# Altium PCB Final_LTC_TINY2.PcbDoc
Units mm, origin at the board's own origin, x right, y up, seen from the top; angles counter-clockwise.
Board outline 34.19 x 13.74 mm, 2 copper layers (Top Layer, Bottom Layer), stack 1.671 mm thick; 36 components, 55 nets, 138 pads, 94 vias.
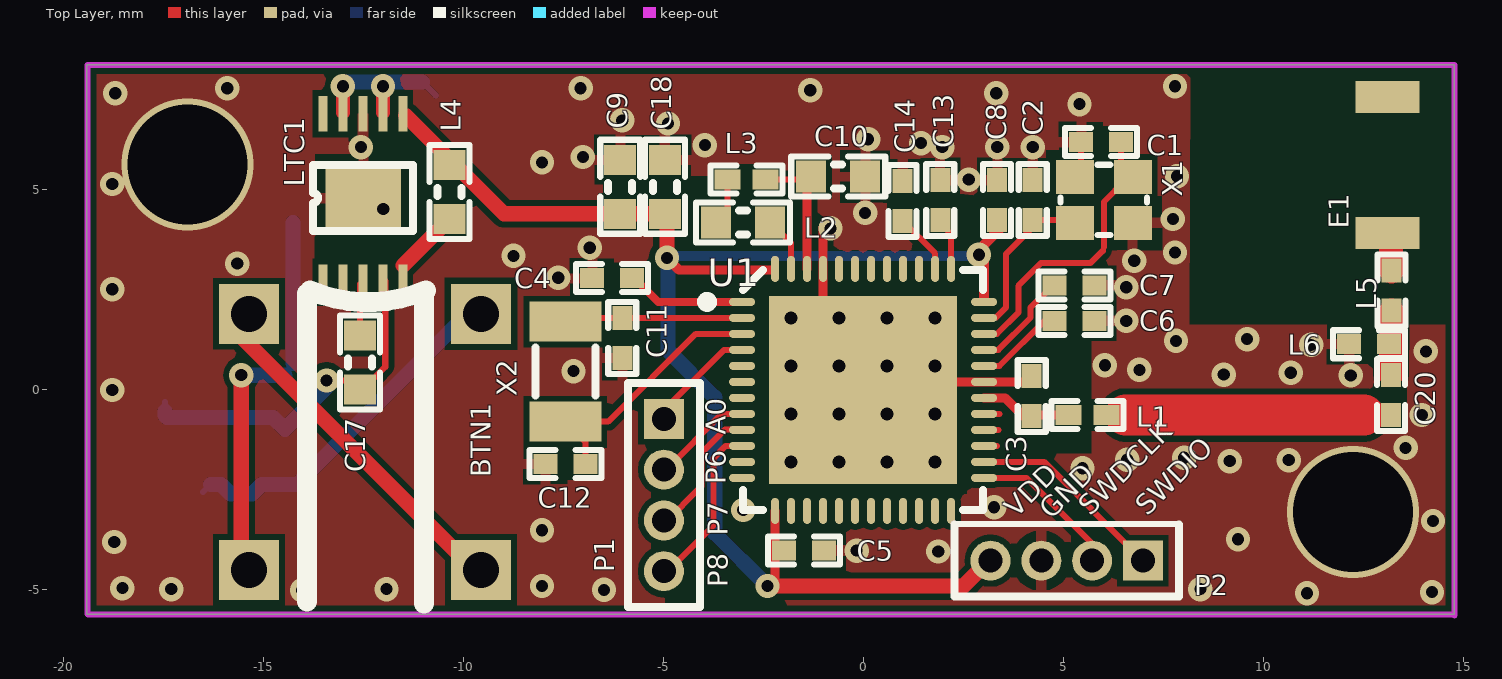
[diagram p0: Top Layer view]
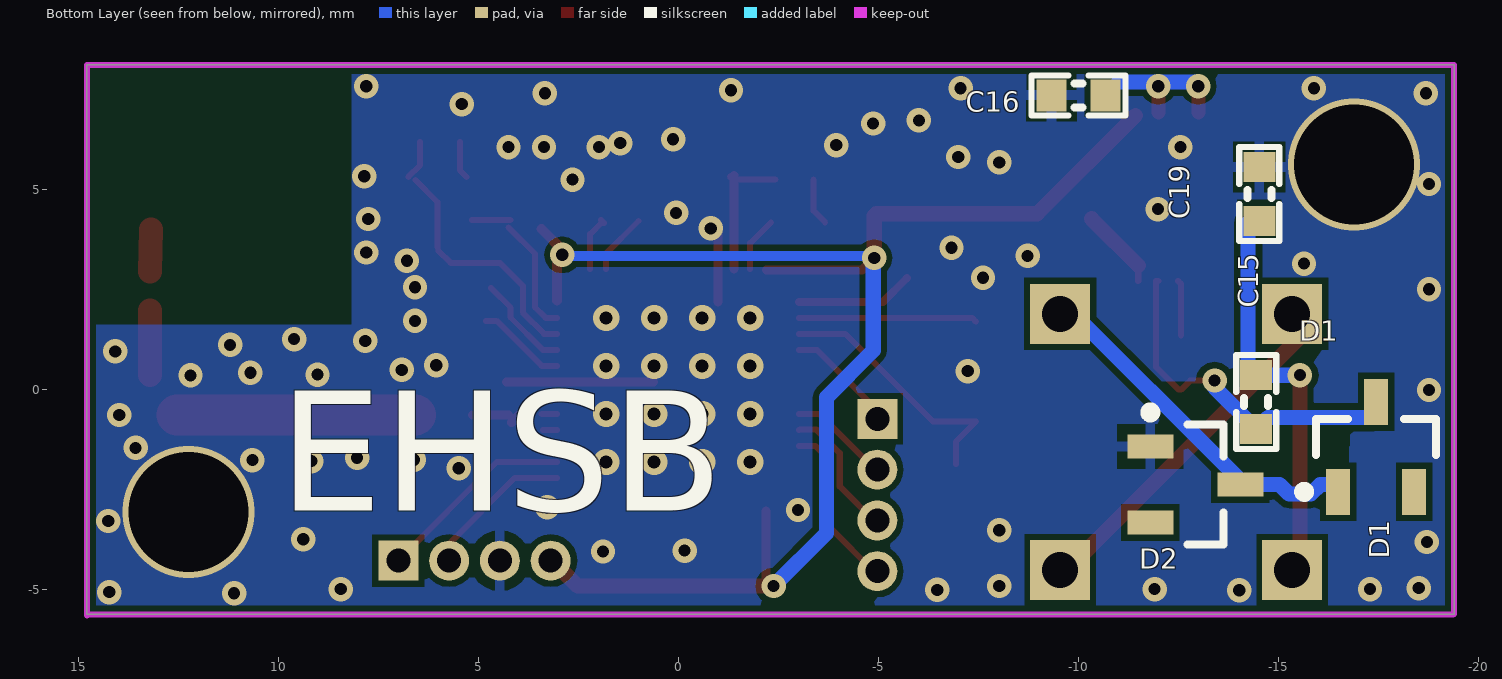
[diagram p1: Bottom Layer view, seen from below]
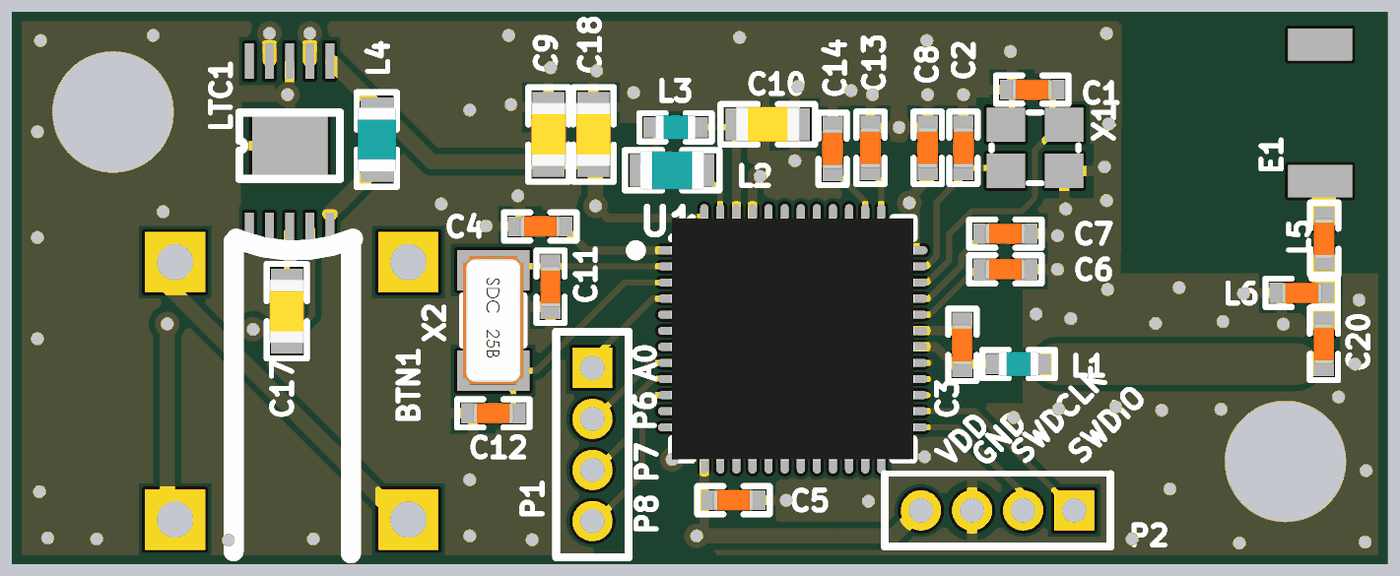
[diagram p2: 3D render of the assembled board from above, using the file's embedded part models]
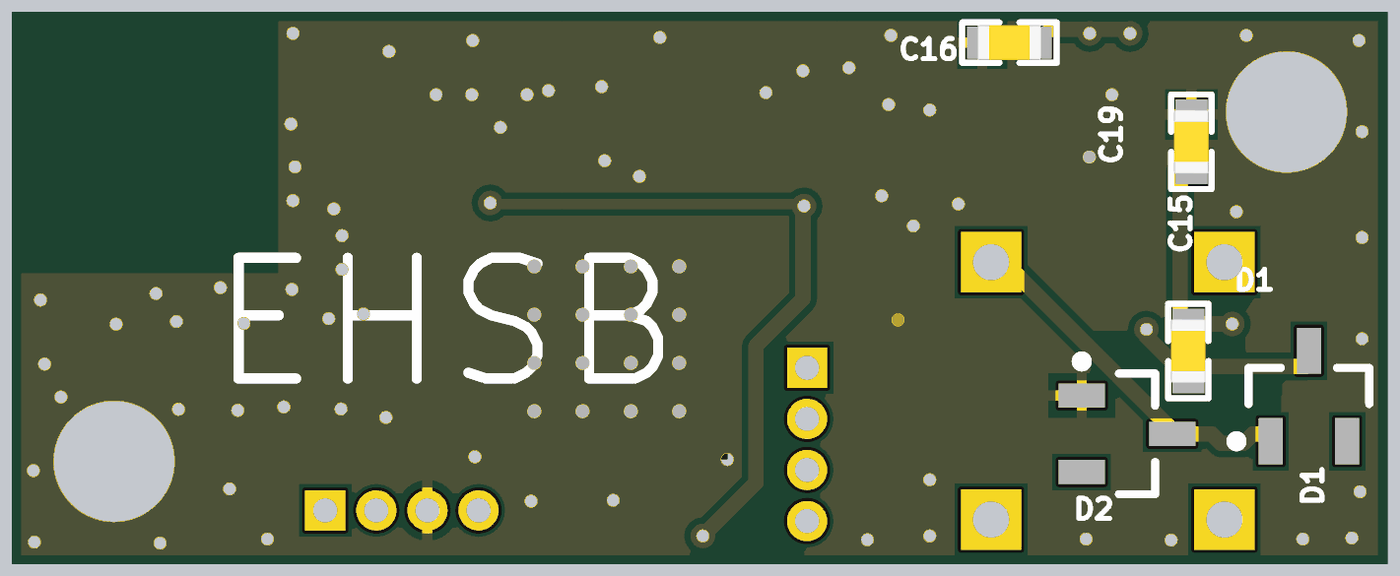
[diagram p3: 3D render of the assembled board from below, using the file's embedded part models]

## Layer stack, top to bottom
Top Solder: solder mask 0.0102, Solder Resist, Dk 3.5
Top Layer: signal copper 0.0356
Dielectric1: core 1.6002, FR-4, Dk 4.8
Bottom Layer: signal copper 0.0356
Bottom Solder: solder mask 0.0102, Solder Resist, Dk 3.5

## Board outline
-19.406,-5.613 14.783,-5.613 14.783,8.128 -19.406,8.128

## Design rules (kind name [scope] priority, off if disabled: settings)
Clearance Polygon_ANT [(InNamedPolygon('Top_Layer-GND')) or (InNamedPolygon('Bottom_Layer-GND')) vs InNet('RF')] p1: gap=0.127 ignorepadtopadclearanceinfootprint=FALSE except(0: Arc-Hole Track-Hole SMDPad-Hole THPad-Hole Via-Hole Fill-Hole Poly-Hole Region-Hole Text-Hole)
Clearance Polygon [(InNamedPolygon('Top_Layer-GND')) or (InNamedPolygon('Bottom_Layer-GND'))] p2: gap=0.254 ignorepadtopadclearanceinfootprint=FALSE except(0: Arc-Hole Track-Hole SMDPad-Hole THPad-Hole Via-Hole Fill-Hole Poly-Hole Region-Hole Text-Hole)
Clearance [All] p3: gap=0.152 ignorepadtopadclearanceinfootprint=FALSE except(0: Arc-Hole Track-Hole SMDPad-Hole THPad-Hole Via-Hole Fill-Hole Poly-Hole Region-Hole Text-Hole)
ComponentClearance [All] p1 off: gap=0.254 collisioncheckmode=3 verticalgap=0.254 showdistances=FALSE
FabricationTestPointUsage TestPointUsage [All] p1: valid=0 allowmultiple=FALSE
FabricationTestpoint Testpoint [All] p1: side=3 testpointundercomponent=TRUE minsize=1.016 maxsize=2.54 preferedsize=1.524 minholesize=0 maxholesize=1.016 preferedholesize=0.813 testpointgrid=0.025 allowsidetop=TRUE allowsidebottom=TRUE usegrid=TRUE gridtolerance=0
Height [All] p1 off: minheight=0 maxheight=25.4 prefheight=12.7
HoleSize [All] p1: absolutevalues=TRUE maxlimit=4.064 minlimit=0.305 maxpercent=80.000 minpercent=20.000
MinimumAnnularRing [All] p1 off: minimumring=0.152
PolygonConnect PolygonConnect_1 [isVia and innet(gnd)] p1: connectstyle=Direct reliefconductorwidth=0.254 reliefentries=4 polygonreliefangle="90 Angle" airgapwidth=0.254
PolygonConnect [All] p2: connectstyle=Relief reliefconductorwidth=0.254 reliefentries=4 polygonreliefangle="90 Angle" airgapwidth=0.254
RoutingVias [All] p1: holewidth=0.406 width=0.813 viastyle="Through Hole" minholewidth=0.254 minwidth=0.254 maxholewidth=0.711 maxwidth=1.27
SilkToSolderMaskClearance SilkscreenOverComponentPads [IsPad] p1: minsilkscreentomaskgap=0.254 clearancetoexposedcopper=TRUE
SolderMaskExpansion [All] p1: expansion=0.076
Width [All] p1: maxlimit=2.54 minlimit=0.152 preferedwidth=0.152
24 further rules are at their usual default settings.

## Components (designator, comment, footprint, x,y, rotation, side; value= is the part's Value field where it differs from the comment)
BTN1 "ZF_button" ZF-button -9.55,1.905 r270 top
C1 "12pF" CAPC1005X04L 5.952,6.198 r180 top
C2 "12pF" CAPC1005X04L 4.242,4.75 r90 top
C3 "0.8pF" CAPC1005X04L 4.216,-0.152 r270 top
C4 "100nF" CAPC1005X04L -6.274,2.794 r180 top
C5 "100nF" CAPC1005X04L -1.473,-4.013 r0 top
C6 "N.C." CAPC1005X04L 5.283,1.727 r180 top
C7 "100pF" CAPC1005X04L 5.283,2.616 r0 top
C8 "100nF" CAPC1005X04L 3.353,4.75 r90 top
C9 "4.7µF" CAPC1608X06L -6.071,5.08 r90 top
C10 "1.0µF" CAPC1608X06L -0.62,5.334 r180 top
C11 "12pF" CAPC1005X04L -6.02,1.295 r270 top
C12 "12pF" CAPC1005X04L -7.442,-1.854 r180 top
C13 "12pF" CAPC1005X04L 1.93,4.75 r90 top
C14 "12pF" CAPC1005X04L 0.991,4.724 r90 top
C15 "47µF" CAPC1608X06L -14.453,-0.305 r270 bottom
C16 "4.7µF" CAPC1608X06L -10.008,7.366 r180 bottom
C17 "1µF" CAPC1608X06L -12.573,0.686 r270 top
C18 "47µF" CAPC1608X06L -4.953,5.08 r270 top
C19 "220µF" CAPC1608X06L -14.529,4.899 r270 bottom
C20 "Cap" CAPC1005X04L 13.199,-0.127 r90 top value=12pF
D1 "Diode 1N4004" SOT-23_N -17.45,-1.422 r90 bottom
D2 "Diode 1N4004" SOT-23_N -12.929,-2.362 r180 bottom
E1 "Antenna" antenne 13.106,5.618 r90 top
L1 "3.9nH" INDC1005X04L 5.613,-0.627 r0 top
L2 "10µH" INDC1608X06L -2.997,4.191 r0 top
L3 "15nH" INDC1005X04L -2.913,5.258 r180 top
L4 "10µH" INDC1608X06L -10.338,4.953 r90 top
L5 "3.3nH" CAPC1005X04L 13.208,2.489 r90 top value=3.9nH
L6 "2.7nH" CAPC1005X04L 12.649,1.143 r180 top value=3.9nH
LTC1 "2x5 Pin" "MSOP10 - duplicate1" -13.503,2.696 r90 top
P1 "MHDR1X4" MHDR1X4 -4.978,-0.722 r270 top
P2 "MHDR1X4" MHDR1X4 6.996,-4.267 r180 top
U1 "nRF52832-QFAA" QFN40P600X600X90-48N 0,0 r0 top locked
X1 "32MHz" BT-XTAL_2016 6.02,4.75 r180 top
X2 "32.768kHz" XTAL_3215 -7.442,0.457 r270 top

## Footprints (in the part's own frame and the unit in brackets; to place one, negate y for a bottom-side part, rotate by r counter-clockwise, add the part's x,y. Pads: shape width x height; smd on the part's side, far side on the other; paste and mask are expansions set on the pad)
antenne [mm]
  rect 0.8x1.6 smd: 1(-1.7,0) 2(1.7,0)
BT-XTAL_2016 [mm] "Crystal 2.0 x 1.6 mm"
  rect 0.95x0.85 smd: 1(-0.725,-0.575) 2(0.725,-0.575) 3(0.725,0.575) 4(-0.725,0.575)
  silkscreen extent -1.08,-0.88 1.08,0.88
CAPC1005X04L [mm] "Chip Capacitor, 2-Leads, Body 1.0x0.5mm, IPC High Density"
  rect 0.6x0.5 smd: 1(-0.5,0) 2(0.5,0)
  silkscreen extent -0.9,-0.35 0.9,0.35, body extent -0.51,-0.25 0.51,0.25, height 0.5
CAPC1608X06L [mm] "Chip Capacitor, 2-Leads, Body 1.6x0.8mm, IPC High Density"
  rect 0.75x0.8 smd: 1(-0.675,0) 2(0.675,0)
  silkscreen extent -1.17,-0.5 1.17,0.5, body extent -0.8,-0.43 0.8,0.43, height 0.8
INDC1005X04L [mm] "Chip Inductor, 2-Leads, Body 1.0x0.5mm, IPC High Density"
  rect 0.65x0.5 smd: 1(-0.475,0) 2(0.475,0)
  silkscreen extent -0.9,-0.35 0.9,0.35, body extent -0.5,-0.3 0.5,0.3, height 0.5
INDC1608X06L [mm]
  rect 0.75x0.8 smd: 1(-0.675,0) 2(0.675,0)
  silkscreen extent -1.17,-0.5 1.18,0.5, body extent -0.8,-0.48 0.8,0.48, height 0.8
MHDR1X4 [mm] "Connector; Header; 4 Position"
  rect 1x1 hole 0.6: 1(0,0)
  round 1 hole 0.6: 2(1.27,0) 3(2.54,0) 4(3.81,0)
  silkscreen extent -0.9,-0.9 4.71,0.9
"MSOP10 - duplicate1" [mm]
  rect 0.889x0.22 smd: 1(0,0) 2(0,-0.5) 3(0,-1) 4(0,-1.5) 5(0,-2) 6(4.211,-2) 7(4.211,-1.5) 8(4.211,-1) 9(4.211,-0.5) 10(4.211,0)
  rect 1.68x1.88 smd: 26(2.105,-1.006)
  silkscreen extent 1.28,-2.25 2.93,0.25
QFN40P600X600X90-48N [mm] "QFN, 48-Leads, Body 6,0x6,0mm (max), Pitch 0,40mm, IPC Medium Density"
  oval 0.65x0.2 smd: 1(-3.025,2.2) 2(-3.025,1.8) 3(-3.025,1.4) 4(-3.025,1) 5(-3.025,0.6) 6(-3.025,0.2) 7(-3.025,-0.2) 8(-3.025,-0.6) 9(-3.025,-1) 10(-3.025,-1.4) 11(-3.025,-1.8) 12(-3.025,-2.2) 25(3.025,-2.2) 26(3.025,-1.8) 27(3.025,-1.4) 28(3.025,-1) 29(3.025,-0.6) 30(3.025,-0.2) 31(3.025,0.2) 32(3.025,0.6) 33(3.025,1) 34(3.025,1.4) 35(3.025,1.8) 36(3.025,2.2)
  oval 0.2x0.65 smd: 13(-2.2,-3.025) 14(-1.8,-3.025) 15(-1.4,-3.025) 16(-1,-3.025) 17(-0.6,-3.025) 18(-0.2,-3.025) 19(0.2,-3.025) 20(0.6,-3.025) 21(1,-3.025) 22(1.4,-3.025) 23(1.8,-3.025) 24(2.2,-3.025) 37(2.2,3.025) 38(1.8,3.025) 39(1.4,3.025) 40(1,3.025) 41(0.6,3.025) 42(0.2,3.025) 43(-0.2,3.025) 44(-0.6,3.025) 45(-1,3.025) 46(-1.4,3.025) 47(-1.8,3.025) 48(-2.2,3.025)
  rect 4.7x4.7 smd: 49(0,0)
  silkscreen extent -4.02,-3 3,3, body extent -3.02,-3.02 3.02,3.02, height 0.86
SOT-23_N [mm] "SOT23, 3-Leads, Body 2.9x1.3mm, Pitch 0.95mm, Lead Span 2.5mm, IPC Medium Density"
  rect 1.15x0.6 smd: 1(-1.125,0.95) 2(-1.125,-0.95) 3(1.125,0)
  silkscreen extent -1.25,-1.5 0.7,1.93, body extent -0.7,-1.5 0.7,1.5, height 1.1
XTAL_3215 [mm] "XTAL SMD 3.2 x 1.5 mm"
  rect 1x1.8 smd: 1(-1.25,0) 2(1.25,0)
  silkscreen extent -0.6,-0.75 0.6,0.75, body extent -1.6,-0.75 1.6,0.75, height 0.81
ZF-button [mm]
  rect 1.5x1.5 hole 0.9: 1(0,0) 2(0,-5.8) 3(6.4,-5.8) 4(6.4,0)
  silkscreen extent -0.58,-4.35 7.24,-1.38

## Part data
C1 C2 C11 C12 C13 C14: library part C0402-12p, "Capacitor, NP0, ±2%"
C3: library part C0402-0.8p, "Capacitor, NP0, ±5%"
C4 C5 C8: library part C0402-100n, "Capacitor, X7R, ±10%"
C6: library part C0402-N.C., "Not mounted"
C7: library part C0402-100p, "Capacitor, NP0, ±5%"
C9: library part C0603-4µ7, "Capacitor, X5R, ±10%"
C10: library part C0603-1µ0, "Capacitor, X7R, ±10%"
C15 C16 C17 C18 C19: "Capacitor, X5R, ±10%", Part Number=C0603-4µ7
C20: "Capacitor"
D1 D2: "1 Amp General Purpose Rectifier"
E1: "Generic Antenna"
L1 L5 L6: library part L0402-3n9, "High frequency chip inductor ±5%", Manufacturer=Murata, Manufacturer Part Number=LQP15MN3N9B02D, Supplier part number=490-1131-1-ND
L2: library part L0603-10µ, "Chip inductor, IDC,min = 50 mA, ±20%", 2nd source part number=178-6105, Manufacturer="Taiyo Yuden", Manufacturer Part Number=LBMF1608T100K, Supplier part number=587-1714-1-ND
L3: library part L0402-15n, "High frequency chip inductor ±10%", 2nd source part number=658-1328, Manufacturer="Taiyo Yuden", Manufacturer Part Number=HK100515NJ-T, Supplier part number=587-1521-1-ND
L4: "Chip inductor, IDC,min = 50 mA, ±20%", 2nd source part number=178-6105, Manufacturer="Taiyo Yuden", Manufacturer Part Number=LBMF1608T100K, Part Number=L0603-10µ, Supplier part number=587-1714-1-ND
P1 P2: "Header, 4-Pin"
U1: "Multi-protocol Bluetooth Low Energy, ANT and 2.4GHz proprietary system-on-chip", Manufacturer="Nordic Semiconductor"
X1: library part XTAL_SMD2016_32MHz_8pF_General, "XTAL SMD 2016, 32MHz, Cl=8pF, Total Tol: ±40ppm"
X2: library part XTAL_SMD3215_32.768kHz_9pF_General, "XTAL SMD 3215, 32.768kHz, Cl=9pF, Total Tol: ±50ppm"

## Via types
v1: diameter 0.61, hole 0.305, Top Layer to Bottom Layer, tented both sides, 76 vias
v2: diameter 0.66, hole 0.33, Top Layer to Bottom Layer, tented both sides, 16 vias
v3: diameter 3.3, hole 3, Top Layer to Bottom Layer, tented both sides, 2 vias

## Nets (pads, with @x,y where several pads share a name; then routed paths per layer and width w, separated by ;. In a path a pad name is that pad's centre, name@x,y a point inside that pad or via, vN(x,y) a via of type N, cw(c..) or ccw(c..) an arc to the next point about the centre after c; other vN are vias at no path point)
DEC1: C4.1 U1.1 | length 2.9
  Top Layer w0.203: C4.1@-5.715,2.794 -5.121,2.2 U1.1
DEC2: C6.2 U1.32 | length 2.2
  Top Layer w0.152: U1.32 3.411,0.6 4.538,1.727 C6.2@4.801,1.727
DEC3: C7.1 U1.33 | length 2.4
  Top Layer w0.152: U1.33 3.38,1 4.191,1.811 4.191,2.062 C7.1@4.675,2.546
DEC4: C10.2 L3.1 U1.46 | length 3.4
  Top Layer w0.152: L3.1 -1.4,5.258 -1.372,5.258 C10.2
  Top Layer w0.229: U1.46 C10.2@-1.4,5.258 ; C10.2@-1.4,5.334 C10.2@-1.4,5.359
GND: C1.2 C2.2 C3.1 C4.2 C5.2 C6.1 C7.2 C8.2 C9.2 C10.1 C11.2 C12.2 C13.2 C14.2 C16.1 C18.1 C19.1 D2.1 L6.2 LTC1.8 LTC1.26 P2.3 U1.31 U1.45 U1.49 X1.2 X1.4 | length 6.5
  Top Layer w0.152: X1.2 5.452,5.482 C1.2
  Top Layer w0.229: U1.49@-1,2.2 U1.45 v1@-1,4.064 ; U1.49@0.618,0.203 C3.1@4.293,0.203
  other v1: 11.1,-5.08 14.224,-5.055 -14.025,-5.006 -6.477,-4.997 -17.297,-4.978 -11.913,-4.978 8.433,-4.978 -18.517,-4.953 -8.026,-4.902 1.88,-4.038 -0.16,-4.016 -18.72,-3.802 9.373,-3.734 -8.026,-3.505 14.249,-3.277 -2.997,-3 3.277,-2.933 5.486,-1.956 9.169,-1.778 6.604,-1.745 10.643,-1.753 8.026,-1.694 13.564,-1.448 13.97,-0.627 -18.771,0 12.192,0.364 9.017,0.383 10.693,0.43 -7.239,0.471 6.909,0.502 6.045,0.618 14.072,0.965 11.201,1.126 7.823,1.227 9.601,1.272 6.579,1.727 -18.771,2.519 6.579,2.565 -7.62,2.806 -15.646,3.16 6.782,3.229 -8.738,3.353 7.798,3.437 -6.833,3.556 -0.813,4.039 7.747,4.275 0.051,4.428 -11.993,4.521 -18.771,5.149 2.642,5.258 7.849,5.342 -8.026,5.69 -7.004,5.825 -12.555,6.071 1.981,6.071 3.353,6.071 4.242,6.071 -3.954,6.121 1.448,6.172 0.127,6.27 -4.875,6.663 -6.02,6.739 5.41,7.145 -18.694,7.417 3.331,7.417 -1.321,7.493 -15.894,7.544 -7.061,7.544 7.798,7.595
  other v2: -1.8,-1.8 -0.6,-1.8 0.6,-1.8 1.8,-1.8 -1.8,-0.6 -0.6,-0.6 0.6,-0.6 1.8,-0.6 -1.8,0.6 -0.6,0.6 0.6,0.6 1.8,0.6 -1.8,1.8 -0.6,1.8 0.6,1.8 1.8,1.8
  other v3: 12.243,-3.048 -16.891,5.639
NetBTN1_1: BTN1.1 D1.1 D2.3 | length 9.4
  Bottom Layer w0.152: D1.1 D1.1@-16.315,-2.362 ; D2.3 -14.054,-2.167 D2.3@-14.007,-2.214 ; BTN1.1@-9.55,2.243 BTN1.1@-9.55,2.336
  Bottom Layer w0.381: D1.1@-16.315,-2.362 -16.054,-2.362 -15.812,-2.603 -15.276,-2.603 -15.035,-2.362 D2.3 ; D2.3@-14.007,-2.214 BTN1.1@-9.55,2.243
NetBTN1_2: BTN1.2 BTN1.4 | length 8.8
  Top Layer w0.152: BTN1.2@-15.544,1.323 BTN1.2@-15.544,1.905 ; BTN1.4@-9.744,-4.495 BTN1.4@-9.744,-4.477
  Top Layer w0.381: BTN1.2@-15.544,1.323 BTN1.4@-9.744,-4.477
NetBTN1_3: BTN1.3 C15.1 C19.2 | length 9.4
  Top Layer w0.381: BTN1.3@-15.544,-4.495 v1@-15.544,0.33
  Bottom Layer w0.381: v1(-15.545,0.37) C15.1 ; C15.1@-14.249,0.66 C19.2@-14.249,4.18
NetC3_2: C3.2 L1.1 U1.30 | length 2.3
  Top Layer w0.152: C3.2 C3.2@4.242,-0.627
  Top Layer w0.229: U1.30 3.553,-0.2 C3.2@4.166,-0.813 ; C3.2@4.242,-0.627 L1.1
NetC11_1: C11.1 U1.2 X2.1 | length 4.5
  Top Layer w0.152: X2.1 -7.349,1.8 U1.2
NetC12_1: C12.1 U1.3 X2.2 | length 6.6
  Top Layer w0.152: C12.1 -6.942,-1.293 X2.2 -6.372,-0.793 -4.18,1.4 U1.3
NetC15_2: C15.2 C17.2 D1.3 LTC1.4 | length 9.1
  Top Layer w0.152: v1(-13.411,0.236) -12.798,0.236 C17.2 -12.511,0.011 -11.944,0.578 -11.944,2.721 LTC1.4@-12.003,2.721
  Bottom Layer w0.152: D1.3@-17.45,-0.533 D1.3 ; v1@-13.411,0.062 v1(-13.411,0.236)
  Bottom Layer w0.381: D1.3@-17.45,-0.533 -17.45,-0.635 -17.399,-0.686 -14.747,-0.686 C15.2 v1@-13.411,0.062
NetC16_2: C16.2 LTC1.7 LTC1.9 | length 3.9
  Top Layer w0.152: v1@-13.005,7.696 v1@-13.003,7.694
  Top Layer w0.35: LTC1.9@-13.003,6.932 v1@-13.003,7.694 ; LTC1.7@-12.003,6.932 v1@-12.003,7.634
  Bottom Layer w0.152: C16.2@-11.013,7.696 C16.2
  Bottom Layer w0.381: v1@-12.954,7.696 C16.2@-11.013,7.696
  other v1: -13.005,7.595 -12.003,7.595
NetC17_1: C17.1 LTC1.3 | length 1.4
  Top Layer w0.152: C17.1 -12.573,2.651 LTC1.3@-12.503,2.721
NetC20_2: C20.2 L5.1 L6.1 | length 2.3
  Top Layer w0.152: C20.2 L6.1@13.199,1.093
  Top Layer w0.6: C20.2 L5.1
NetE1_1: E1.1 L5.2 | length 1
  Top Layer w0.6: E1.1@13.183,4.013 L5.2@13.208,2.966
NetL2_1: L2.1 L3.2 | length 1.2
  Top Layer w0.152: L2.1 -3.388,4.475 L3.2
NetL2_2: L2.2 U1.47 | length 1.4
  Top Layer w0.152: L2.2 -1.8,3.669 U1.47
NetL4_1: L4.1 LTC1.5 | length 2
  Top Layer w0.152: LTC1.5@-11.503,2.721 LTC1.5@-11.503,3.113
  Top Layer w0.381: LTC1.5@-11.503,3.113 L4.1
P0.02/AIN0: P1.1 U1.4 | length 2.8
  Top Layer w0.152: P1.1 -4.978,-0.508 -3.47,1 U1.4
P0.03/AIN1: U1.5
P0.04/AIN2: U1.6
P0.05/AIN3: U1.7
P0.06: P1.2 U1.8 | length 2.5
  Top Layer w0.152: P1.2 -4.925,-1.992 -3.533,-0.6 U1.8
P0.07: P1.3 U1.9 | length 3.4
  Top Layer w0.152: P1.3@-4.972,-3.345 -4.04,-2.413 -4.04,-1.577 -3.454,-0.991 -3.034,-0.991 U1.9
P0.08: P1.4 U1.10 | length 4.3
  Top Layer w0.152: P1.4@-4.972,-4.615 -3.735,-3.378 -3.735,-1.703 -3.432,-1.4 U1.10
P0.09: U1.11
P0.10: U1.12
P0.11: U1.14
P0.12: U1.15
P0.13: U1.16
P0.14: U1.17
P0.15: U1.18
P0.16: U1.19
P0.17: U1.20
P0.18: U1.21
P0.19: U1.22
P0.20: U1.23
P0.21: U1.24
P0.22: U1.27 | length 0.3
  Top Layer w0.152: U1.27 U1.27@3.349,-1.4
P0.23: U1.28 | length 0.4
  Top Layer w0.152: U1.28 3.38,-1
P0.24: U1.29 | length 0.4
  Top Layer w0.152: U1.29 3.411,-0.6
P0.25: C13.1 U1.37 | length 1.4
  Top Layer w0.152: C13.1 1.854,4.173 1.923,4.173 2.2,3.896 U1.37
P0.26: C14.1 U1.38 | length 1.5
  Top Layer w0.152: C14.1 1.8,3.415 U1.38
P0.27: U1.39
P0.28/AIN4: U1.40
P0.29/AIN5: U1.41
P0.30/AIN6: U1.42
P0.31/AIN7: U1.43
RF: C20.1 L1.2 | length 6
  Top Layer w1.035: 6.571,-0.627 12.522,-0.627
SWDCLK: P2.2 U1.25 | length 3.8
  Top Layer w0.152: U1.25 4.08,-2.2 5.726,-3.846 P2.2
SWDIO: P2.1 U1.26 | length 5
  Top Layer w0.152: U1.26 4.529,-1.8 P2.1
VDD_NRF: C5.1 C8.1 C9.1 C18.2 L4.2 LTC1.6 P2.4 U1.13 U1.36 U1.48 | length 38.1
  Top Layer w0.152: C18.2 C18.2@-4.902,4.354
  Top Layer w0.229: v1(-4.902,3.302) -4.6,3 U1.48@-2.21,3 ; v1(-2.388,-4.902) -2.2,-4.715 U1.13
  Top Layer w0.254: v1@2.837,3.446 C8.1@3.416,4.026 ; U1.36@3.025,2.235 v1@3.025,3.302
  Top Layer w0.381: LTC1.6@-11.433,6.863 -8.976,4.405 C9.1 C18.2 ; v1(-4.902,3.302) C18.2@-4.902,4.354 ; v1(-2.388,-4.902) 2.515,-4.902 P2.4@3.175,-4.242
  Bottom Layer w0.254: v1@-5.006,3.353 v1@2.769,3.353
  Bottom Layer w0.381: v1@-4.877,3.277 -4.877,0.986 -3.707,-0.184 -3.707,-3.583 v1(-2.388,-4.902)
  other v1: 2.896,3.378
XC1: C1.1 U1.34 X1.1 | length 7.1
  Top Layer w0.152: U1.34 3.349,1.4 3.883,1.934 3.883,2.603 4.456,3.175 5.69,3.175 5.994,3.48 ; 6.02,3.581 6.02,4.699 X1.1@6.571,5.25 ; C1.1 6.452,5.618 X1.1
XC2: C2.1 U1.35 X1.3 | length 3.9
  Top Layer w0.152: U1.35 3.315,1.8 3.579,2.064 3.579,3.401 C2.1@4.242,4.064 ; C2.1@4.191,4.25 C2.1 X1.3@5.148,4.25
pads on no net: D1.2 D2.2 E1.2 LTC1.1 LTC1.2 LTC1.10 U1.44

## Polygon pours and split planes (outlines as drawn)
GND on Bottom Layer "Bottom Layer-GND" (solid, pour order 1006): -19.406,8.128 -19.38,8.103 14.783,8.103 14.783,-5.537 -19.38,-5.537 -19.406,-5.563
GND on Top Layer "Top Layer-GND" (solid, pour order 1004): -19.406,8.128 -19.38,8.153 14.783,8.153 14.783,-5.512 14.757,-5.537 -19.431,-5.537

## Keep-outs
Keep-Out Layer:
  lines w0.152: -19.393,-5.601 -19.393,8.128 -19.38,8.128 14.783,8.128 14.783,-5.639 14.757,-5.613 -19.38,-5.613 -19.393,-5.601

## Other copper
Top Layer:
  pour cut-out: -4.978,-5.397 -4.94,-5.359 -2.337,-5.359 -2.337,-3.432 -2.34,-3.429 -3.57,-3.429 -3.57,-3.469 -4.953,-4.852 -4.953,-5.338
  pour cut-out: -3.556,-3.467
  pour cut-out: -12.314,5.715 -12.337,5.739 -12.337,6.401 -11.345,6.401 -11.328,6.384 -11.43,6.282 -11.43,5.69
  pour cut-out: -11.379,4.061 -11.379,6.359 -10.846,5.825 -10.846,5.283 -10.693,5.131 -10.054,5.131 -10.054,5.076 -9.881,4.902 -10.084,4.699 -10.744,4.699 -10.82,4.623 -10.82,4.115 -10.936,4.115 -11.24,3.81
  pour cut-out: -13.716,3.238 -13.716,3.835 -13.691,3.861 -13.669,3.839 -11.4,3.839 -11.4,3.56 -11.663,3.298 -11.913,3.298
  pour cut-out: 2.298,4.923 2.37,4.851 2.921,4.851
  pour cut-out: -6.502,4.782 -6.502,5.359 -6.477,5.385 -6.452,5.359 -3.81,5.359 -3.81,4.67
  pour cut-out: 8.179,8.128 14.681,8.128 14.681,1.626 8.153,1.626
  pour cut-out: 14.681,8.128
  pour cut-out: 5.715,-1.6 2.972,-1.6 2.972,1.295 5.715,1.295
Bottom Layer:
  pour cut-out: -16.764,-1.422 -16.789,-1.397 -16.789,-0.977
  pour cut-out: -15.824,0.6 -15.824,0.762 -16.129,1.067
  pour cut-out: -15.773,-0.381 -15.874,-0.28 -15.874,0.146 -15.875,0.145 -15.812,0.083 -15.812,-0.439
  pour cut-out: -16.764,-1.956 -16.764,-1.372 -14.554,-1.372 -13.005,0.178 -13.005,0.203 -12.014,0.203 -14.072,-1.854 -14.072,-1.981 -14.605,-1.981 -14.808,-2.184 -14.859,-2.134 -16.027,-2.134
  pour cut-out: -4.75,-0.239 -4.627,-0.117 -4.269,-0.117 -3.954,-0.432 -4.013,-0.491 -4.013,-3.704 -2.54,-5.177 -2.591,-5.228 -2.591,-5.448 -4.877,-5.448
  pour cut-out: 14.668,8.128 8.166,8.128 8.166,1.626 14.694,1.626

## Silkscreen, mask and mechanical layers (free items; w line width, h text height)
Top Overlay:
  lines w0.152: 2.311,-3.348 7.857,-3.348
  text "A0" at -3.429,-1.118 h0.5 r90
  text "P6" at -3.432,-2.358 h0.5 r90
  text "SWDCLK" at 5.677,-3.175 h0.5 r45
  text "SWDIO" at 7.1,-3.175 h0.5 r45
  text "VDD" at 3.835,-3.226 h0.5 r45
  text "GND" at 4.699,-3.251 h0.5 r45
  text "P7" at -3.388,-3.642 h0.5 r90
  text "P8" at -3.388,-4.928 h0.5 r90
Bottom Overlay:
  text "EHSB" at 9.982,-3.023 h3
  text "D1" at -17.78,-4.216 h0.5 r270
